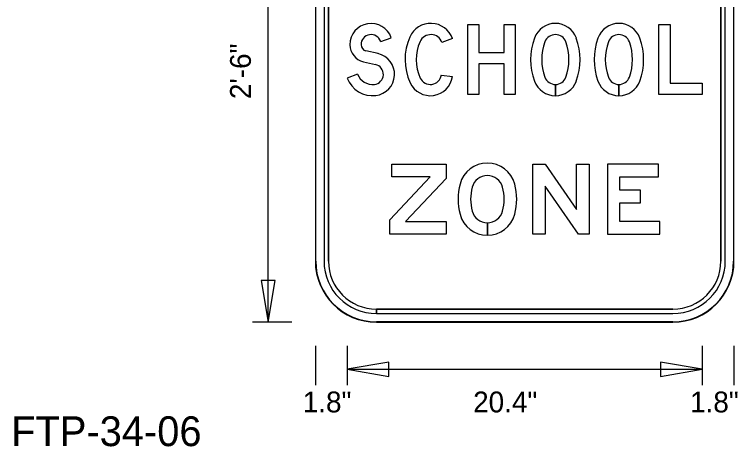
# Model space of a CAD drawing. Extents: x 0 to 770, y 0 to 495.
# Drawn here: x 199.3 to 320.7, y 199.2 to 271.7 of the extents above; entities that cross this region are included whole.
import ezdxf

# ---------------------------------------------------------------- set-up
doc = ezdxf.new("R2010")
doc.units = 0
for name, color, linetype in [('Dimension', 7, 'Continuous'), ('GSBWFill', 7, 'Continuous'), ('GSColorFill', 7, 'Continuous'), ('GSDims', 7, 'Continuous'), ('GSOutline', 7, 'Continuous'), ('TextStructures', 7, 'Continuous')]:
    doc.layers.add(name, color=color, linetype=linetype)

msp = doc.modelspace()

# ---------------------------------------------------------------- linework, layer by layer
at = {"layer": 'Dimension'}
for points in [[(241.92, 220.07), (243.1, 227.09), (240.73, 227.09)], [(255.15, 212.17), (262.17, 210.98), (262.17, 213.35)], [(314.77, 212.17), (307.76, 213.35), (307.76, 210.98)]]:
    msp.add_lwpolyline(points, close=True, dxfattribs=at)
at = {"layer": 'GSBWFill'}
for p, q in [((249.82, 297.67), (249.82, 230.32)), ((251.29, 297.67), (251.29, 230.32)), ((252.02, 230.32), (252.02, 297.67)), ((317.91, 297.67), (317.91, 230.32)), ((318.64, 230.32), (318.64, 297.67)), ((320.1, 230.32), (320.1, 297.67)), ((260.8, 267.19), (262.57, 267.8)), ((272.84, 267.66), (271.08, 267.02)), ((260.34, 265.15), (258.32, 265.6)), ((257.9, 263.78), (259.92, 263.32)), ((256.91, 261.7), (255.15, 261.04)), ((270.99, 261.55), (272.84, 261.28)), ((290.12, 258.08), (290.12, 259.96)), ((290.12, 259.96), (290.12, 258.08)), ((300.78, 258.08), (300.78, 259.96)), ((300.78, 259.96), (300.78, 258.08)), ((278.7, 234.66), (278.7, 236.76)), ((278.7, 236.76), (278.7, 234.66)), ((260.07, 221.54), (260.07, 222.27)), ((309.85, 222.27), (260.08, 222.27)), ((260.08, 222.27), (260.08, 221.54)), ((260.08, 221.54), (309.85, 221.54)), ((260.07, 220.07), (309.85, 220.07))]:
    msp.add_line(p, q, dxfattribs=at)
for points in [[(275.42, 270), (277.29, 270), (277.29, 265.32), (281.51, 265.32), (281.51, 270), (283.38, 270), (283.38, 258.29), (281.51, 258.29), (281.51, 263.44), (277.29, 263.44), (277.29, 258.29), (275.42, 258.29)], [(309.38, 260.16), (314.77, 260.16), (314.77, 258.29), (307.51, 258.29), (307.51, 270), (309.38, 270)], [(271.78, 236.97), (271.78, 234.86), (262.3, 234.86), (262.3, 237.26), (269.1, 244.47), (262.65, 244.47), (262.65, 246.57), (271.78, 246.57), (271.78, 244.17), (264.93, 236.97)], [(295.8, 246.57), (295.8, 234.86), (293.98, 234.86), (288.42, 242.88), (288.42, 234.86), (286.31, 234.86), (286.31, 246.57), (288.43, 246.57), (293.69, 238.98), (293.69, 246.57)], [(307.63, 236.97), (300.95, 236.97), (300.95, 240.12), (304.41, 240.12), (304.41, 242.23), (300.95, 242.23), (300.95, 244.47), (307.45, 244.47), (307.45, 246.57), (298.84, 246.57), (298.84, 234.86), (307.63, 234.86)]]:
    msp.add_lwpolyline(points, close=True, dxfattribs=at)
for centre, radius, start, end in [((259.19, 266.63), 3.57, 19.1395, 180), ((259.19, 266.63), 1.7, 19.1395, 180), ((258.55, 266.63), 2.93, 180, 257.1915), ((258.55, 266.63), 1.05, 180, 257.1915), ((259.54, 261.66), 3.57, 276.7854, 77.1915), ((259.54, 261.66), 1.7, 276.7854, 77.1915), ((259.43, 262.65), 4.57, 200.6442, 276.7854), ((259.43, 262.65), 2.69, 200.6442, 276.7854), ((278.7, 242.03), 4.75, 14.9618, 165.0382), ((278.7, 242.03), 2.64, 14.9618, 165.0382), ((283.62, 240.72), 9.84, 165.0382, 194.9618), ((273.78, 240.72), 9.84, 345.0382, 14.9618), ((283.62, 240.72), 7.73, 165.0382, 194.9618), ((273.78, 240.72), 7.73, 345.0382, 14.9618), ((278.7, 239.4), 4.75, 194.9618, 270), ((278.7, 239.4), 2.64, 194.9618, 270), ((278.7, 239.4), 2.64, 270.0127, 345.0382), ((278.7, 239.4), 4.75, 270.0071, 345.0382), ((260.07, 230.32), 10.25, 180, 270), ((260.07, 230.32), 8.79, 180, 270), ((260.07, 230.32), 8.05, 180, 270), ((309.85, 230.32), 8.79, 270, 0), ((309.85, 230.32), 8.05, 270, 0), ((309.85, 230.32), 10.25, 270, 0)]:
    msp.add_arc(centre, radius, start, end, dxfattribs=at)
for centre, major_axis, start_param, end_param in [((269.21, 266.34), (0, 3.87), 5.061866, 7.434148), ((290.12, 266.46), (0, 3.75), 5.063177, 7.503193), ((300.78, 266.46), (0, 3.75), 5.063177, 7.503193), ((269.21, 266.34), (0, 1.99), 5.061866, 7.434148), ((290.12, 266.46), (0, 1.87), 5.063177, 7.503193), ((300.78, 266.46), (0, 1.87), 5.063177, 7.503193), ((274.13, 264.14), (0, 9.25), 1.150963, 2.004476), ((274.13, 264.14), (0, 7.38), 1.150963, 2.004476), ((296.44, 264.14), (0, 10.48), 1.220008, 1.921585), ((296.44, 264.14), (0, 8.61), 1.220008, 1.921585), ((283.79, 264.14), (0, 8.61), 4.361601, 5.063177), ((283.79, 264.14), (0, 10.48), 4.361601, 5.063177), ((307.1, 264.14), (0, 10.48), 1.220008, 1.921585), ((307.1, 264.14), (0, 8.61), 1.220008, 1.921585), ((294.45, 264.14), (0, 8.61), 4.361601, 5.063177), ((294.45, 264.14), (0, 10.48), 4.361601, 5.063177), ((269.13, 261.83), (0, 3.75), 2.004476, 4.564141), ((269.13, 261.83), (0, 1.87), 2.004476, 4.564141), ((290.12, 261.83), (0, 1.87), 1.921585, 3.141593), ((290.12, 261.83), (0, 1.87), 3.141905, 4.361601), ((300.78, 261.83), (0, 1.87), 1.921585, 3.141593), ((300.78, 261.83), (0, 1.87), 3.141905, 4.361601), ((290.12, 261.83), (0, 3.75), 1.921585, 3.141593), ((290.12, 261.83), (0, 3.75), 3.141749, 4.361601), ((300.78, 261.83), (0, 3.75), 1.921585, 3.141593), ((300.78, 261.83), (0, 3.75), 3.141749, 4.361601)]:
    msp.add_ellipse(centre, major_axis=major_axis, ratio=0.999993, start_param=start_param, end_param=end_param, dxfattribs=at)
at = {"layer": 'GSColorFill'}
for p, q in [((249.82, 297.67), (249.82, 230.32)), ((249.82, 297.67), (249.82, 230.32)), ((249.9, 230.32), (249.9, 297.67)), ((251.29, 297.67), (251.29, 230.32)), ((252.02, 230.32), (252.02, 297.67)), ((317.91, 297.67), (317.91, 230.32)), ((318.64, 230.32), (318.64, 297.67)), ((320.03, 297.67), (320.03, 230.32)), ((320.1, 230.32), (320.1, 297.67)), ((320.1, 230.32), (320.1, 297.67)), ((260.8, 267.19), (262.57, 267.8)), ((272.84, 267.66), (271.08, 267.02)), ((260.34, 265.15), (258.32, 265.6)), ((257.9, 263.78), (259.92, 263.32)), ((256.91, 261.7), (255.15, 261.04)), ((270.99, 261.55), (272.84, 261.28)), ((290.12, 258.08), (290.12, 259.96)), ((290.12, 259.96), (290.12, 258.08)), ((300.78, 258.08), (300.78, 259.96)), ((300.78, 259.96), (300.78, 258.08)), ((278.7, 234.66), (278.7, 236.76)), ((278.7, 236.76), (278.7, 234.66)), ((260.07, 221.54), (260.07, 222.27)), ((309.85, 222.27), (260.08, 222.27)), ((260.08, 222.27), (260.08, 221.54)), ((260.08, 221.54), (309.85, 221.54)), ((260.07, 220.07), (260.07, 220.15)), ((309.85, 220.15), (260.07, 220.15)), ((260.07, 220.15), (260.07, 220.07)), ((260.07, 220.07), (309.85, 220.07)), ((260.07, 220.07), (309.85, 220.07))]:
    msp.add_line(p, q, dxfattribs=at)
for points in [[(275.42, 270), (277.29, 270), (277.29, 265.32), (281.51, 265.32), (281.51, 270), (283.38, 270), (283.38, 258.29), (281.51, 258.29), (281.51, 263.44), (277.29, 263.44), (277.29, 258.29), (275.42, 258.29)], [(309.38, 260.16), (314.77, 260.16), (314.77, 258.29), (307.51, 258.29), (307.51, 270), (309.38, 270)], [(271.78, 236.97), (271.78, 234.86), (262.3, 234.86), (262.3, 237.26), (269.1, 244.47), (262.65, 244.47), (262.65, 246.57), (271.78, 246.57), (271.78, 244.17), (264.93, 236.97)], [(295.8, 246.57), (295.8, 234.86), (293.98, 234.86), (288.42, 242.88), (288.42, 234.86), (286.31, 234.86), (286.31, 246.57), (288.43, 246.57), (293.69, 238.98), (293.69, 246.57)], [(307.63, 236.97), (300.95, 236.97), (300.95, 240.12), (304.41, 240.12), (304.41, 242.23), (300.95, 242.23), (300.95, 244.47), (307.45, 244.47), (307.45, 246.57), (298.84, 246.57), (298.84, 234.86), (307.63, 234.86)]]:
    msp.add_lwpolyline(points, close=True, dxfattribs=at)
for centre, radius, start, end in [((259.19, 266.63), 3.57, 19.1395, 180), ((259.19, 266.63), 1.7, 19.1395, 180), ((258.55, 266.63), 2.93, 180, 257.1915), ((258.55, 266.63), 1.05, 180, 257.1915), ((259.54, 261.66), 3.57, 276.7854, 77.1915), ((259.54, 261.66), 1.7, 276.7854, 77.1915), ((259.43, 262.65), 4.57, 200.6442, 276.7854), ((259.43, 262.65), 2.69, 200.6442, 276.7854), ((278.7, 242.03), 4.75, 14.9618, 165.0382), ((278.7, 242.03), 2.64, 14.9618, 165.0382), ((283.62, 240.72), 9.84, 165.0382, 194.9618), ((273.78, 240.72), 9.84, 345.0382, 14.9618), ((283.62, 240.72), 7.73, 165.0382, 194.9618), ((273.78, 240.72), 7.73, 345.0382, 14.9618), ((278.7, 239.4), 4.75, 194.9618, 270), ((278.7, 239.4), 2.64, 194.9618, 270), ((278.7, 239.4), 2.64, 270.0127, 345.0382), ((278.7, 239.4), 4.75, 270.0071, 345.0382), ((260.07, 230.32), 10.25, 180, 270), ((260.07, 230.32), 10.25, 180, 270), ((260.07, 230.32), 10.18, 180, 270), ((260.07, 230.32), 8.79, 180, 270), ((260.07, 230.32), 8.05, 180, 270), ((309.85, 230.32), 10.25, 270, 0), ((309.85, 230.32), 8.79, 270, 0), ((309.85, 230.32), 8.05, 270, 0), ((309.85, 230.32), 10.25, 270, 0), ((309.85, 230.32), 10.18, 270, 0)]:
    msp.add_arc(centre, radius, start, end, dxfattribs=at)
for centre, major_axis, start_param, end_param in [((269.21, 266.34), (0, 3.87), 5.061866, 7.434148), ((290.12, 266.46), (0, 3.75), 5.063177, 7.503193), ((300.78, 266.46), (0, 3.75), 5.063177, 7.503193), ((269.21, 266.34), (0, 1.99), 5.061866, 7.434148), ((290.12, 266.46), (0, 1.87), 5.063177, 7.503193), ((300.78, 266.46), (0, 1.87), 5.063177, 7.503193), ((274.13, 264.14), (0, 9.25), 1.150963, 2.004476), ((274.13, 264.14), (0, 7.38), 1.150963, 2.004476), ((296.44, 264.14), (0, 10.48), 1.220008, 1.921585), ((296.44, 264.14), (0, 8.61), 1.220008, 1.921585), ((283.79, 264.14), (0, 8.61), 4.361601, 5.063177), ((283.79, 264.14), (0, 10.48), 4.361601, 5.063177), ((307.1, 264.14), (0, 10.48), 1.220008, 1.921585), ((307.1, 264.14), (0, 8.61), 1.220008, 1.921585), ((294.45, 264.14), (0, 8.61), 4.361601, 5.063177), ((294.45, 264.14), (0, 10.48), 4.361601, 5.063177), ((269.13, 261.83), (0, 3.75), 2.004476, 4.564141), ((269.13, 261.83), (0, 1.87), 2.004476, 4.564141), ((290.12, 261.83), (0, 1.87), 1.921585, 3.141593), ((290.12, 261.83), (0, 1.87), 3.141905, 4.361601), ((300.78, 261.83), (0, 1.87), 1.921585, 3.141593), ((300.78, 261.83), (0, 1.87), 3.141905, 4.361601), ((290.12, 261.83), (0, 3.75), 1.921585, 3.141593), ((290.12, 261.83), (0, 3.75), 3.141749, 4.361601), ((300.78, 261.83), (0, 3.75), 1.921585, 3.141593), ((300.78, 261.83), (0, 3.75), 3.141749, 4.361601)]:
    msp.add_ellipse(centre, major_axis=major_axis, ratio=0.999993, start_param=start_param, end_param=end_param, dxfattribs=at)
at = {"layer": 'GSDims'}
for p, q in [((241.92, 220.07), (241.92, 307.92)), ((245.87, 220.07), (239.28, 220.07)), ((249.82, 216.12), (249.82, 209.53)), ((255.15, 216.12), (255.15, 209.53)), ((255.15, 216.12), (255.15, 209.53)), ((314.77, 216.12), (314.77, 209.53)), ((314.77, 216.12), (314.77, 209.53)), ((320.1, 216.12), (320.1, 209.53)), ((255.15, 212.17), (314.77, 212.17))]:
    msp.add_line(p, q, dxfattribs=at)
at = {"layer": 'GSOutline'}
for p, q in [((249.82, 297.67), (249.82, 230.32)), ((251.29, 297.67), (251.29, 230.32)), ((252.02, 297.67), (252.02, 230.32)), ((317.91, 230.32), (317.91, 297.67)), ((318.64, 230.32), (318.64, 297.67)), ((320.1, 230.32), (320.1, 297.67)), ((260.8, 267.19), (262.57, 267.8)), ((272.84, 267.66), (271.08, 267.02)), ((260.34, 265.15), (258.32, 265.6)), ((257.9, 263.78), (259.92, 263.32)), ((256.91, 261.7), (255.15, 261.04)), ((270.99, 261.55), (272.84, 261.28)), ((260.07, 222.27), (309.85, 222.27)), ((260.07, 221.54), (309.85, 221.54)), ((260.07, 220.07), (309.85, 220.07))]:
    msp.add_line(p, q, dxfattribs=at)
for points in [[(275.42, 270), (277.29, 270), (277.29, 265.32), (281.51, 265.32), (281.51, 270), (283.38, 270), (283.38, 258.29), (281.51, 258.29), (281.51, 263.44), (277.29, 263.44), (277.29, 258.29), (275.42, 258.29)], [(309.38, 260.16), (314.77, 260.16), (314.77, 258.29), (307.51, 258.29), (307.51, 270), (309.38, 270)], [(271.78, 236.97), (271.78, 234.86), (262.3, 234.86), (262.3, 237.26), (269.1, 244.47), (262.65, 244.47), (262.65, 246.57), (271.78, 246.57), (271.78, 244.17), (264.93, 236.97)], [(295.8, 246.57), (295.8, 234.86), (293.98, 234.86), (288.42, 242.88), (288.42, 234.86), (286.31, 234.86), (286.31, 246.57), (288.43, 246.57), (293.69, 238.98), (293.69, 246.57)], [(307.63, 236.97), (300.95, 236.97), (300.95, 240.12), (304.41, 240.12), (304.41, 242.23), (300.95, 242.23), (300.95, 244.47), (307.45, 244.47), (307.45, 246.57), (298.84, 246.57), (298.84, 234.86), (307.63, 234.86)]]:
    msp.add_lwpolyline(points, close=True, dxfattribs=at)
for centre, radius, start, end in [((259.19, 266.63), 3.57, 19.1395, 180), ((259.19, 266.63), 1.7, 19.1395, 180), ((258.55, 266.63), 2.93, 180, 257.1915), ((258.55, 266.63), 1.05, 180, 257.1915), ((259.54, 261.66), 3.57, 276.7854, 77.1915), ((259.54, 261.66), 1.7, 276.7854, 77.1915), ((259.43, 262.65), 4.57, 200.6442, 276.7854), ((259.43, 262.65), 2.69, 200.6442, 276.7854), ((278.7, 242.03), 4.75, 14.9618, 165.0382), ((278.7, 242.03), 2.64, 14.9618, 165.0382), ((283.62, 240.72), 9.84, 165.0382, 194.9618), ((273.78, 240.72), 9.84, 345.0382, 14.9618), ((283.62, 240.72), 7.73, 165.0382, 194.9618), ((273.78, 240.72), 7.73, 345.0382, 14.9618), ((278.7, 239.4), 4.75, 194.9618, 345.0382), ((278.7, 239.4), 2.64, 194.9618, 345.0382), ((260.07, 230.32), 10.25, 180, 270), ((260.07, 230.32), 8.79, 180, 270), ((260.07, 230.32), 8.05, 180, 270), ((309.85, 230.32), 8.79, 270, 0), ((309.85, 230.32), 8.05, 270, 0), ((309.85, 230.32), 10.25, 270, 0)]:
    msp.add_arc(centre, radius, start, end, dxfattribs=at)
for centre, major_axis, start_param, end_param in [((269.21, 266.34), (0, 3.87), 5.061866, 7.434148), ((290.12, 266.46), (0, 3.75), 5.063177, 7.503193), ((300.78, 266.46), (0, 3.75), 5.063177, 7.503193), ((269.21, 266.34), (0, 1.99), 5.061866, 7.434148), ((290.12, 266.46), (0, 1.87), 5.063177, 7.503193), ((300.78, 266.46), (0, 1.87), 5.063177, 7.503193), ((274.13, 264.14), (0, 9.25), 1.150963, 2.004476), ((274.13, 264.14), (0, 7.38), 1.150963, 2.004476), ((296.44, 264.14), (0, 10.48), 1.220008, 1.921585), ((296.44, 264.14), (0, 8.61), 1.220008, 1.921585), ((283.79, 264.14), (0, 8.61), 4.361601, 5.063177), ((283.79, 264.14), (0, 10.48), 4.361601, 5.063177), ((307.1, 264.14), (0, 10.48), 1.220008, 1.921585), ((307.1, 264.14), (0, 8.61), 1.220008, 1.921585), ((294.45, 264.14), (0, 8.61), 4.361601, 5.063177), ((294.45, 264.14), (0, 10.48), 4.361601, 5.063177), ((269.13, 261.83), (0, 3.75), 2.004476, 4.564141), ((269.13, 261.83), (0, 1.87), 2.004476, 4.564141), ((290.12, 261.83), (0, 1.87), 1.921585, 4.361601), ((300.78, 261.83), (0, 1.87), 1.921585, 4.361601), ((290.12, 261.83), (0, 3.75), 1.921585, 4.361601), ((300.78, 261.83), (0, 3.75), 1.921585, 4.361601)]:
    msp.add_ellipse(centre, major_axis=major_axis, ratio=0.999993, start_param=start_param, end_param=end_param, dxfattribs=at)

# ---------------------------------------------------------------- texts
at = {"layer": 'TextStructures'}
msp.add_text('2\'-6"', height=3.5, rotation=90, dxfattribs=at).set_placement((239, 257.51))
for s, height, p in [('1.8"', 3.5, (247.71, 204.94)), ('20.4"', 3.5, (276.31, 204.94)), ('1.8"', 3.5, (312.73, 204.94)), ('FTP-34-06', 5, (198.76, 199.28))]:
    msp.add_text(s, height=height, dxfattribs=at).set_placement(p)

doc.saveas('drawing.dxf')
